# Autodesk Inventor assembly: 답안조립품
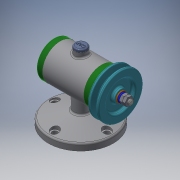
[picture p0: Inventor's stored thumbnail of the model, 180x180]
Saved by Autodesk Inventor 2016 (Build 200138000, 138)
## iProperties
Created: 2018-12
Part Number: 답안조립품
Material: 일반
Document SubType Name: Assembly
Designer: USER
Author: USER
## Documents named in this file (15)
- C:\Users\USER\Desktop\481207V1064\답안조립품.iam
- C:\Users\USER\Desktop\481207V1064\본체.ipt
- C:\Users\USER\Desktop\481207V1064\V벨트풀리.ipt
- C:\Users\USER\Desktop\481207V1064\고무캡.ipt
- C:\Users\USER\Desktop\481207V1064\너트 M8.ipt
- 너트 M8.ipt
- C:\Users\USER\Desktop\481207V1064\뒤커버.ipt
- C:\Users\USER\Desktop\481207V1064\베어링 15 x 32 x 9.ipt
- C:\Users\USER\Desktop\481207V1064\볼트 M4 x 12.ipt
- C:\Users\USER\Desktop\481207V1064\스프링와셔 8.ipt
- C:\Users\USER\Desktop\481207V1064\앞커버.ipt
- C:\Users\USER\Desktop\481207V1064\오일 실 15 25 7.ipt
- C:\Users\USER\Desktop\481207V1064\와셔 8x17.ipt
- C:\Users\USER\Desktop\481207V1064\축.ipt
- C:\Users\USER\Desktop\481207V1064\키 3 x 3 x 12.ipt
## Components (2 placed, 2 different names)
1. V벨트풀리:1
2. 고무캡:1
